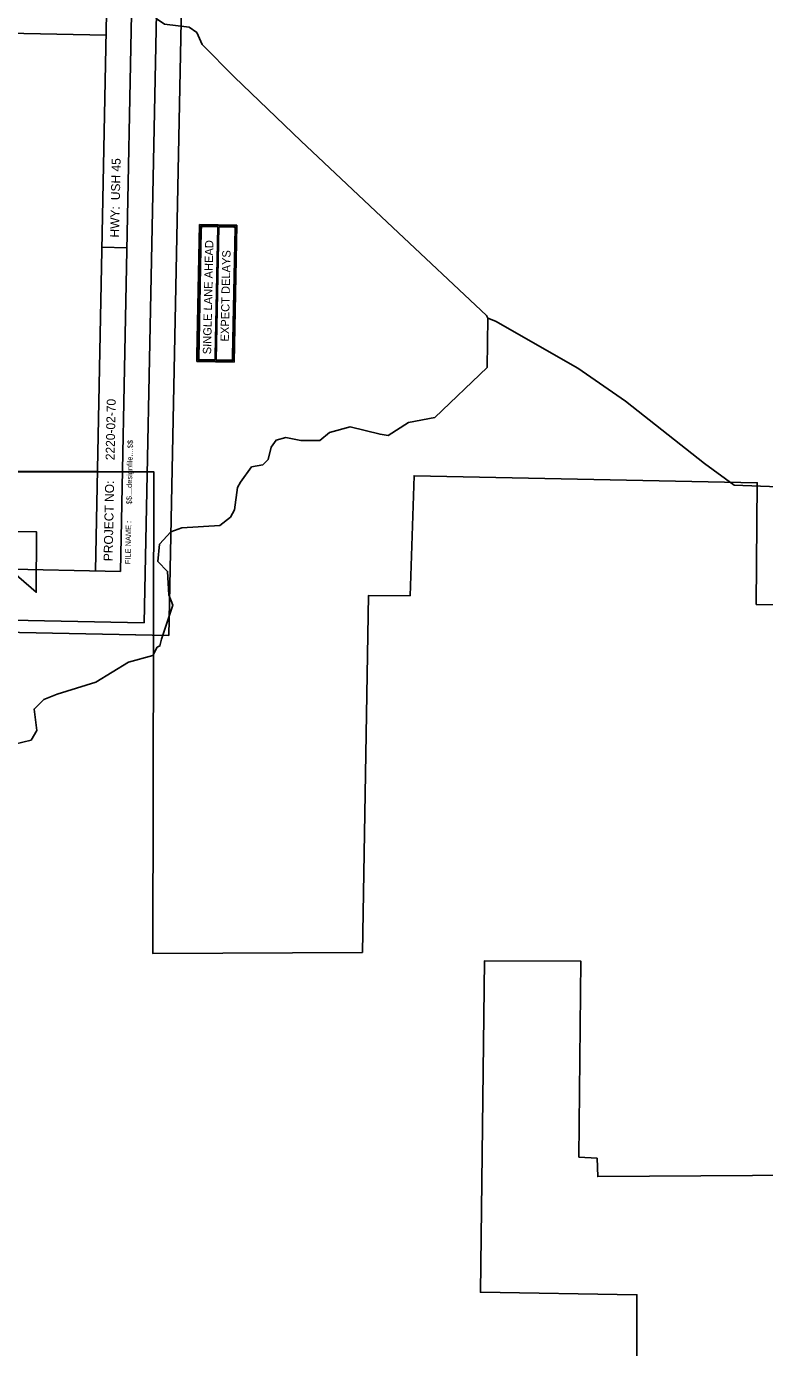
# Model space of a CAD drawing. Extents: x 331323 to 388339, y 121519 to 205315.
# Drawn here: x 366276 to 375161, y 121519 to 137595 of the extents above; entities that cross this region are included whole.
import ezdxf

# ---------------------------------------------------------------- set-up
doc = ezdxf.new("R2010")
doc.units = 0
for name, color, linetype in [('Level 21', 7, 'Continuous'), ('Level 4', 7, 'Continuous'), ('Level 57', 7, 'Continuous'), ('P_RDWY_Text', 7, 'Continuous'), ('P_SGN_Cell', 7, 'Continuous'), ('PLT_Sheet_Border', 7, 'Continuous'), ('PLT_Sheet_Info', 7, 'Continuous')]:
    doc.layers.add(name, color=color, linetype=linetype)

msp = doc.modelspace()

# ---------------------------------------------------------------- linework, layer by layer
at = {"layer": 'Level 21'}
for points in [[(377063, 130598), (375063, 130636), (375076, 132102), (370943, 132185), (370895, 130740), (370392, 130742), (370319, 126443), (367795, 126431), (367808, 132231), (366120, 132233), (366136, 131513), (366392, 131512), (366390, 130783), (366031, 131091), (365085, 131112), (365090, 131495), (364323, 131507), (364297, 130440), (364589, 130440), (364573, 129673), (363929, 129678), (363912, 128375), (362626, 128410), (362594, 121807)], [(373627, 121585), (373626, 122321), (371741, 122350), (371792, 126343), (372951, 126337), (372927, 123979), (373147, 123965), (373155, 123744), (376259, 123765), (376259, 123923), (376481, 123924), (376480, 123673), (376361, 123676), (376356, 123482), (376520, 123475), (376526, 123697), (376586, 123696), (376590, 123384), (376923, 123375), (376912, 121519)]]:
    msp.add_lwpolyline(points, dxfattribs=at)
at = {"layer": 'Level 4'}
for points in [[(358426, 137554), (363663, 137565), (367234, 137492)], [(363948, 132237), (367128, 132236)]]:
    msp.add_lwpolyline(points, dxfattribs=at)
at = {"layer": 'Level 57'}
for points in [[(366907, 140244), (366940, 140211), (366955, 140052), (366988, 139985), (367035, 139685), (367214, 139108), (367237, 138900), (367318, 138699), (367417, 138556), (367681, 138270), (367771, 138086), (367834, 137694), (367934, 137627), (368234, 137590), (368325, 137523), (368390, 137381), (368779, 136986), (369580, 136220), (370688, 135177), (371813, 134116), (371829, 134083)], [(366127, 128951), (366328, 128999), (366396, 129115), (366365, 129374), (366483, 129489), (366642, 129555), (367110, 129700), (367504, 129939), (367797, 130019), (367848, 130119), (367881, 130135), (367899, 130218), (368036, 130625), (367987, 130751), (367973, 131034), (367857, 131152), (367876, 131360), (368011, 131509), (368145, 131558), (368604, 131587), (368730, 131686), (368781, 131777), (368816, 132043), (368850, 132110), (368985, 132292), (369119, 132316), (369186, 132382), (369221, 132531), (369280, 132614), (369397, 132646), (369580, 132611), (369806, 132609), (369923, 132708), (370174, 132773), (370532, 132686), (370632, 132669), (370875, 132825), (371193, 132889), (371824, 133491), (371829, 134083)], [(371829, 134083), (371921, 134049), (372916, 133481), (373488, 133084), (374440, 132334), (374796, 132073), (378189, 131942)]]:
    msp.add_lwpolyline(points, dxfattribs=at)
at = {"layer": 'P_RDWY_Text'}
msp.add_lwpolyline([(354791, 130528), (355202, 150924), (368399, 150658), (367988, 130262)], close=True, dxfattribs=at)
at = {"layer": 'P_SGN_Cell'}
for p, q in [((368327, 133635), (368359, 135212)), ((368808, 135203), (368359, 135212)), ((368775, 135194), (368391, 135202)), ((368775, 133554), (368808, 135203)), ((368367, 135139), (368336, 133595)), ((368379, 135138), (368348, 133595)), ((368367, 135139), (368368, 135179)), ((368379, 135138), (368380, 135178)), ((368577, 135185), (368391, 135189)), ((368546, 133631), (368577, 135185)), ((368590, 135185), (368557, 133580)), ((368775, 135181), (368590, 135185)), ((368755, 133627), (368786, 135170)), ((368798, 135170), (368766, 133587)), ((368327, 133635), (368326, 133563)), ((368546, 133631), (368545, 133580)), ((368755, 133627), (368754, 133587)), ((368775, 133554), (368326, 133563)), ((368545, 133580), (368359, 133584)), ((368742, 133564), (368359, 133571)), ((368743, 133576), (368557, 133580))]:
    msp.add_line(p, q, dxfattribs=at)
for centre, radius, start, end in [((368391, 135178), 23.4, 88.8462, 178.8462), ((368391, 135178), 10.9, 88.8462, 178.8462), ((368775, 135170), 23.4, 358.8462, 88.8462), ((368775, 135170), 10.9, 358.8462, 88.8462), ((368359, 133595), 23.4, 178.8462, 268.8462), ((368359, 133595), 10.9, 178.8462, 268.8462), ((368743, 133587), 23.4, 268.8462, 358.8462), ((368743, 133587), 10.9, 268.8462, 358.8462)]:
    msp.add_arc(centre, radius, start, end, dxfattribs=at)
at = {"layer": 'PLT_Sheet_Border'}
for points in [[(367988, 130262), (368399, 150658), (355202, 150924), (354791, 130528)], [(367691, 130412), (368091, 150268), (355494, 150522), (355094, 130666)]]:
    msp.add_lwpolyline(points, close=True, dxfattribs=at)
at = {"layer": 'PLT_Sheet_Info'}
for p, q in [((367104, 131039), (367484, 149935)), ((367404, 131033), (367784, 149929)), ((367482, 134932), (367182, 134938)), ((367404, 131033), (355406, 131274)), ((367988, 130262), (368000, 130862)), ((367988, 130262), (367388, 130274))]:
    msp.add_line(p, q, dxfattribs=at)

# ---------------------------------------------------------------- texts
at = {"layer": 'P_SGN_Cell'}
for s, p in [('SINGLE LANE AHEAD', (368497, 133648)), ('EXPECT DELAYS', (368710, 133802))]:
    msp.add_text(s, height=100, rotation=88.8462, dxfattribs=at).set_placement(p)
at = {"layer": 'PLT_Sheet_Info'}
for s, height, p in [('USH 45          ', 108, (367398, 135504)), ('HWY:', 108, (367388, 135054)), ('2220-02-70', 108, (367334, 132372)), ('$$....designfile....$$', 64.8, (367540, 131840)), ('PROJECT NO:', 108, (367310, 131155)), ('FILE NAME :', 64.8, (367525, 131120))]:
    msp.add_text(s, height=height, rotation=88.8462, dxfattribs=at).set_placement(p)

doc.saveas('drawing.dxf')
